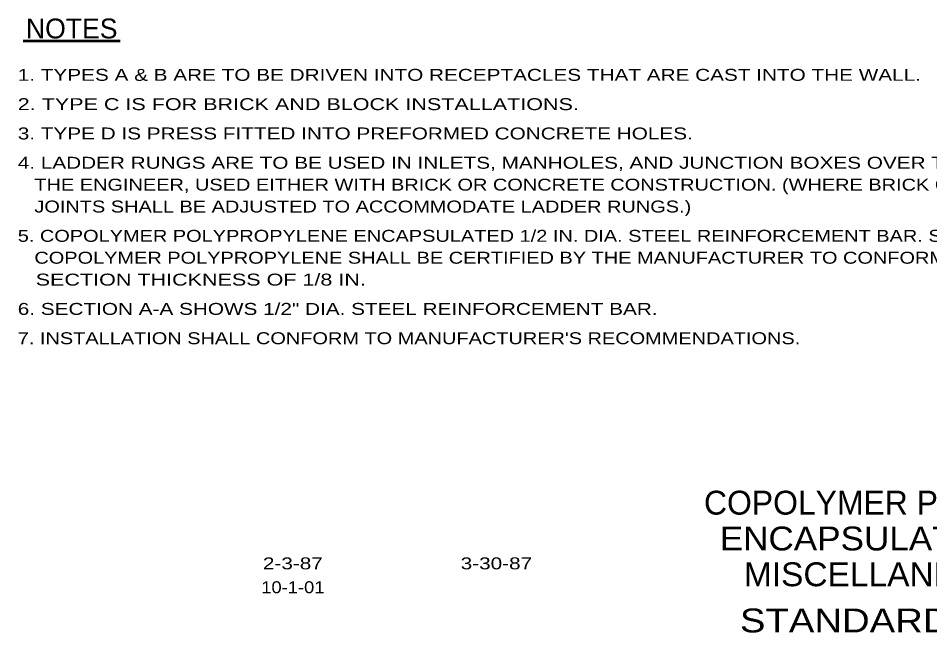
# Model space of a CAD drawing. Extents: x 15 to 140, y -57 to 117.
# Drawn here: x 17.7 to 95.7, y -57.3 to -4.8 of the extents above; entities that cross this region are included whole.
import ezdxf
from ezdxf.enums import TextEntityAlignment as Align

# ---------------------------------------------------------------- set-up
doc = ezdxf.new("R2010")
doc.units = 0
doc.header["$LTSCALE"] = 0.41
doc.layers.add('13', color=7, linetype='Continuous', lineweight=53)

msp = doc.modelspace()

# ---------------------------------------------------------------- linework, layer by layer
at = {"layer": '13'}
msp.add_line((18.1387, -6.7391), (26.4236, -6.7391), dxfattribs=at)

# ---------------------------------------------------------------- texts
for s, height, p in [('NOTES', 1.7, (22.2811, -6.5266)), ('COPOLYMER POLYPROPYLENE STEEL', 2.04, (102.1278, -47.2139))]:
    msp.add_text(s, height=height, dxfattribs=at).set_placement(p, align=Align.CENTER)
for s, width, p in [('1. TYPES A & B ARE TO BE DRIVEN INTO RECEPTACLES THAT ARE CAST INTO THE WALL.', 1.3, (17.6659, -10.1484)), ('2. TYPE C IS FOR BRICK AND BLOCK INSTALLATIONS. ', 1.35, (17.6659, -12.6525)), ('3. TYPE D IS PRESS FITTED INTO PREFORMED CONCRETE HOLES.', 1.3, (17.6659, -15.1566)), ('4. LADDER RUNGS ARE TO BE USED IN INLETS, MANHOLES, AND JUNCTION BOXES OVER THREE FEET IN DEPTH OR AS DIRECTED BY ', 1.3, (17.6659, -17.6607)), ('   THE ENGINEER, USED EITHER WITH BRICK OR CONCRETE CONSTRUCTION. (WHERE BRICK CONSTRUCTION IS EMPLOYED, THE MORTER', 1.25, (17.6659, -19.5307)), ('   JOINTS SHALL BE ADJUSTED TO ACCOMMODATE LADDER RUNGS.)', 1.25, (17.6659, -21.4007)), ('5. COPOLYMER POLYPROPYLENE ENCAPSULATED 1/2 IN. DIA. STEEL REINFORCEMENT BAR. STEEL SHALL CONFORM TO ASTM 615 GRADE 60.', 1.25, (17.6659, -23.9048)), ('   COPOLYMER POLYPROPYLENE SHALL BE CERTIFIED BY THE MANUFACTURER TO CONFORM TO ASTM D 4101 AND HAVE A MINIMUM EXPOSED', 1.25, (17.6659, -25.7748)), ('   SECTION THICKNESS OF 1/8 IN.', 1.35, (17.6659, -27.6448)), ('6. SECTION A-A SHOWS 1/2" DIA. STEEL REINFORCEMENT BAR. ', 1.3, (17.6659, -30.1489)), ("7. INSTALLATION SHALL CONFORM TO MANUFACTURER'S RECOMMENDATIONS. ", 1.25, (17.6659, -32.653))]:
    msp.add_text(s, height=1.02, dxfattribs=dict(at, width=width)).set_placement(p)
for s, height, width, p in [('ENCAPSULATED LADDER RUNGS', 2.04, 1.1, (102.1278, -50.2739)), ('2-3-87', 1.02, 1.3, (41.1945, -51.8911)), ('3-30-87', 1.02, 1.3, (58.6029, -51.8911)), ('MISCELLANEOUS STRUCTURES', 2.04, 1.05, (102.1278, -53.3339)), ('10-1-01', 1.02, 1.15, (41.1945, -53.9311)), ('STANDARD NO.     MD 383.92', 2.04, 1.2, (102.0788, -57.2805))]:
    msp.add_text(s, height=height, dxfattribs=dict(at, width=width)).set_placement(p, align=Align.CENTER)

doc.saveas('drawing.dxf')
